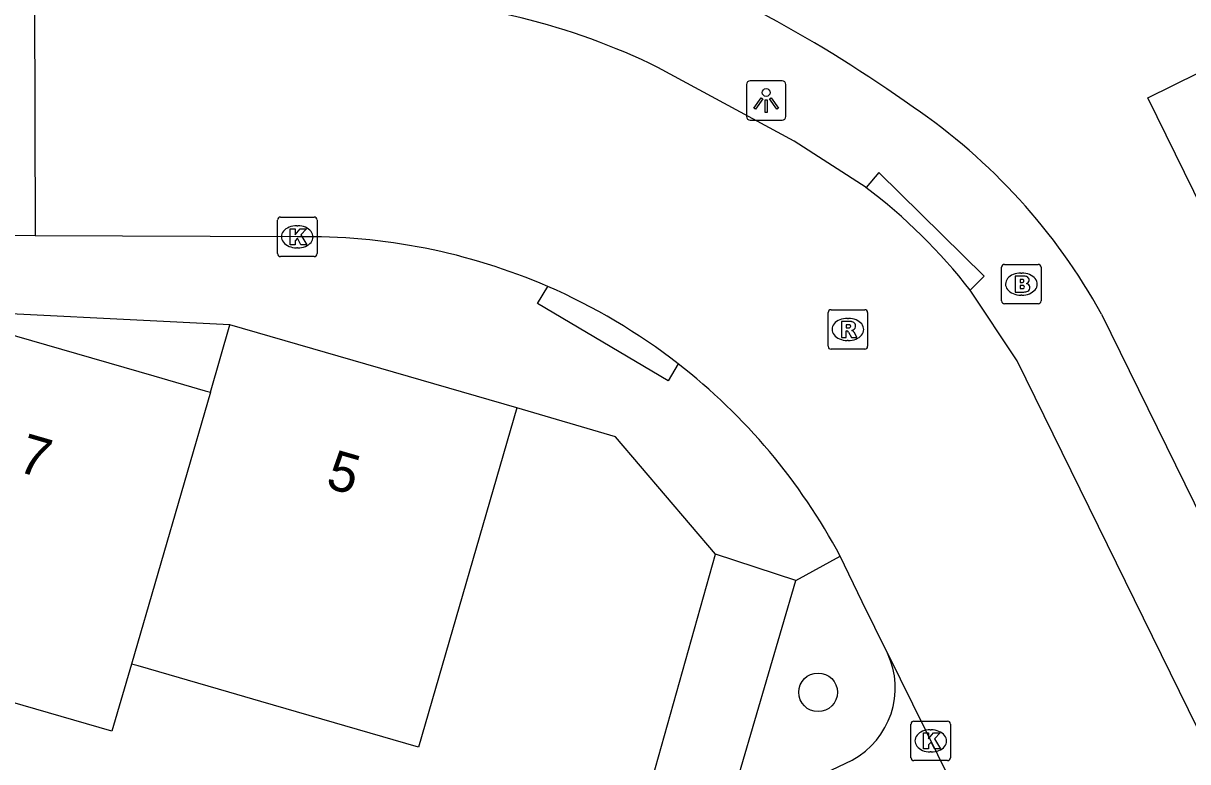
# Model space of a CAD drawing. Extents: x 159718 to 160783, y 383290 to 384030.
# Drawn here: x 160053.1 to 160082.59, y 383412.13 to 383430.82 of the extents above; entities that cross this region are included whole.
import ezdxf

# ---------------------------------------------------------------- set-up
doc = ezdxf.new("R2010")
doc.units = 0
for name, color, linetype in [('IMGEO_Boom', 7, 'Continuous'), ('IMGEO_Brandkraan', 7, 'Continuous'), ('IMGEO_Kolk', 7, 'Continuous'), ('IMGEO_Lichtpunt', 7, 'Continuous'), ('IMGEO_Pand', 7, 'Continuous'), ('IMGEO_Pand_nummerreeks', 7, 'Continuous'), ('IMGEO_Parkeervlak_open', 7, 'Continuous'), ('IMGEO_Rijbaan_lokaal_open', 7, 'Continuous'), ('IMGEO_Rioolput', 7, 'Continuous'), ('IMGEO_Voetpad_open', 7, 'Continuous')]:
    doc.layers.add(name, color=color, linetype=linetype)

msp = doc.modelspace()

# ---------------------------------------------------------------- linework, layer by layer
at = {"layer": 'IMGEO_Boom'}
msp.add_circle((160073.229, 383413.882), 0.489, dxfattribs=at)
at = {"layer": 'IMGEO_Brandkraan'}
for p, q in [((160077.875, 383423.791), (160077.875, 383424.643)), ((160077.95, 383424.717), (160078.802, 383424.717)), ((160078.876, 383424.643), (160078.876, 383423.791)), ((160078.363, 383424.497), (160078.388, 383424.497)), ((160078.802, 383423.717), (160077.95, 383423.717)), ((160078.386, 383423.937), (160078.361, 383423.937))]:
    msp.add_line(p, q, dxfattribs=at)
for points in [[(160077.875, 383423.791), (160077.875, 383424.643)], [(160077.95, 383424.717), (160078.802, 383424.717)], [(160078.876, 383424.643), (160078.876, 383423.791)], [(160078.223, 383424.417), (160078.223, 383424.017), (160078.436, 383424.017)], [(160078.454, 383424.417), (160078.223, 383424.417)], [(160078.402, 383424.336), (160078.348, 383424.336), (160078.348, 383424.26)], [(160078.348, 383424.26), (160078.401, 383424.26)], [(160078.41, 383424.184), (160078.348, 383424.184), (160078.348, 383424.103)], [(160078.348, 383424.103), (160078.41, 383424.103)], [(160078.802, 383423.717), (160077.95, 383423.717)]]:
    msp.add_lwpolyline(points, dxfattribs=at)
for centre, radius, start, end in [((160077.952, 383424.641), 0.0765, 91.552, 178.448), ((160077.952, 383424.641), 0.0765, 91.552, 178.448), ((160078.8, 383424.641), 0.0765, 1.552, 88.448), ((160078.8, 383424.641), 0.0765, 1.552, 88.448), ((160078.403, 383424.298), 0.0379, 267.8285, 90.9355), ((160078.458, 383424.272), 0.145, 59.4692, 91.5367), ((160078.483, 383424.319), 0.0922, 285.5137, 58.1501), ((160078.411, 383424.143), 0.0404, 269.8759, 90.5077), ((160078.442, 383424.268), 0.251, 268.6676, 293.5347), ((160078.488, 383424.127), 0.105, 301.3115, 78.989), ((160077.952, 383423.793), 0.0765, 181.552, 268.448), ((160077.952, 383423.793), 0.0765, 181.552, 268.448), ((160078.8, 383423.793), 0.0765, 271.552, 358.448), ((160078.8, 383423.793), 0.0765, 271.552, 358.448)]:
    msp.add_arc(centre, radius, start, end, dxfattribs=at)
for centre, major_axis, ratio, start_param, end_param in [((160078.362, 383424.217), (-0.387, 0.002), 0.722429, 4.712389, 7.853982), ((160078.387, 383424.217), (-0.39, 0.002), 0.717154, 1.570796, 4.712389)]:
    msp.add_ellipse(centre, major_axis=major_axis, ratio=ratio, start_param=start_param, end_param=end_param, dxfattribs=at)
at = {"layer": 'IMGEO_Kolk'}
for p, q in [((160059.54, 383424.988), (160059.54, 383425.84)), ((160059.615, 383425.914), (160060.467, 383425.914)), ((160060.541, 383425.84), (160060.541, 383424.988)), ((160060.028, 383425.694), (160060.053, 383425.694)), ((160060.051, 383425.134), (160060.026, 383425.134)), ((160060.467, 383424.914), (160059.615, 383424.914)), ((160075.581, 383412.227), (160075.581, 383413.079)), ((160075.656, 383413.153), (160076.508, 383413.153)), ((160076.582, 383413.079), (160076.582, 383412.227)), ((160076.069, 383412.933), (160076.094, 383412.933)), ((160076.092, 383412.373), (160076.067, 383412.373)), ((160076.508, 383412.153), (160075.656, 383412.153))]:
    msp.add_line(p, q, dxfattribs=at)
for points in [[(160059.54, 383424.988), (160059.54, 383425.84)], [(160059.615, 383425.914), (160060.467, 383425.914)], [(160060.541, 383425.84), (160060.541, 383424.988)], [(160059.861, 383425.614), (160059.984, 383425.614), (160059.984, 383425.463), (160060.114, 383425.614), (160060.278, 383425.614), (160060.132, 383425.463), (160060.285, 383425.214), (160060.133, 383425.214), (160060.048, 383425.378), (160059.984, 383425.311), (160059.984, 383425.214), (160059.861, 383425.214), (160059.861, 383425.614)], [(160060.467, 383424.914), (160059.615, 383424.914)], [(160075.581, 383412.227), (160075.581, 383413.079)], [(160075.656, 383413.153), (160076.508, 383413.153)], [(160076.582, 383413.079), (160076.582, 383412.227)], [(160075.902, 383412.853), (160076.025, 383412.853), (160076.025, 383412.702), (160076.155, 383412.853), (160076.319, 383412.853), (160076.173, 383412.702), (160076.326, 383412.453), (160076.174, 383412.453), (160076.089, 383412.617), (160076.025, 383412.55), (160076.025, 383412.453), (160075.902, 383412.453), (160075.902, 383412.853)], [(160076.508, 383412.153), (160075.656, 383412.153)]]:
    msp.add_lwpolyline(points, dxfattribs=at)
for centre, start, end in [((160059.617, 383425.838), 91.552, 178.448), ((160059.617, 383425.838), 91.552, 178.448), ((160060.465, 383425.838), 1.552, 88.448), ((160060.465, 383425.838), 1.552, 88.448), ((160059.617, 383424.99), 181.552, 268.448), ((160059.617, 383424.99), 181.552, 268.448), ((160060.465, 383424.99), 271.552, 358.448), ((160060.465, 383424.99), 271.552, 358.448), ((160075.658, 383413.077), 91.552, 178.448), ((160075.658, 383413.077), 91.552, 178.448), ((160076.506, 383413.077), 1.552, 88.448), ((160076.506, 383413.077), 1.552, 88.448), ((160075.658, 383412.229), 181.552, 268.448), ((160075.658, 383412.229), 181.552, 268.448), ((160076.506, 383412.229), 271.552, 358.448), ((160076.506, 383412.229), 271.552, 358.448)]:
    msp.add_arc(centre, 0.0765, start, end, dxfattribs=at)
for centre, major_axis, ratio, start_param, end_param in [((160060.027, 383425.414), (-0.387, 0.002), 0.722429, 4.712389, 7.853982), ((160060.052, 383425.414), (-0.39, 0.002), 0.717154, 1.570796, 4.712389), ((160076.068, 383412.653), (-0.387, 0.002), 0.722429, 4.712389, 7.853982), ((160076.093, 383412.653), (-0.39, 0.002), 0.717154, 1.570796, 4.712389)]:
    msp.add_ellipse(centre, major_axis=major_axis, ratio=ratio, start_param=start_param, end_param=end_param, dxfattribs=at)
at = {"layer": 'IMGEO_Lichtpunt'}
for p, q in [((160071.415, 383429.269), (160071.415, 383428.462)), ((160071.415, 383429.269), (160071.415, 383428.462)), ((160072.317, 383429.364), (160071.509, 383429.364)), ((160072.317, 383429.364), (160071.509, 383429.364)), ((160072.411, 383428.462), (160072.411, 383429.269)), ((160072.411, 383428.462), (160072.411, 383429.269)), ((160071.509, 383428.368), (160072.317, 383428.368)), ((160071.509, 383428.368), (160072.317, 383428.368))]:
    msp.add_line(p, q, dxfattribs=at)
for points in [[(160071.789, 383428.933), (160071.828, 383428.905), (160071.64, 383428.643), (160071.602, 383428.67), (160071.789, 383428.933)], [(160071.891, 383428.885), (160071.938, 383428.885), (160071.938, 383428.563), (160071.891, 383428.563), (160071.891, 383428.885)], [(160072.001, 383428.905), (160072.039, 383428.932), (160072.226, 383428.67), (160072.187, 383428.642), (160072.001, 383428.905)]]:
    msp.add_lwpolyline(points, dxfattribs=at)
msp.add_circle((160071.914, 383429.067), 0.0994, dxfattribs=at)
for centre, start, end in [((160071.509, 383429.269), 90, 180), ((160071.509, 383429.269), 90, 180), ((160072.317, 383429.269), 0, 90), ((160072.317, 383429.269), 0, 90), ((160071.509, 383428.462), 180, 270), ((160071.509, 383428.462), 180, 270), ((160072.317, 383428.462), 270, 0), ((160072.317, 383428.462), 270, 360)]:
    msp.add_arc(centre, 0.0946, start, end, dxfattribs=at)
at = {"layer": 'IMGEO_Pand'}
for points in [[(160084.135, 383423.723), (160081.575, 383428.935), (160086.063, 383431.14), (160088.858, 383432.513), (160091.41, 383427.319)], [(160050.589, 383423.578), (160056.413, 383421.892), (160057.713, 383421.516), (160057.84, 383421.479)], [(160057.84, 383421.479), (160058.335, 383423.186)], [(160065.601, 383421.083), (160058.335, 383423.186)], [(160057.84, 383421.479), (160055.843, 383414.597)], [(160065.601, 383421.083), (160063.114, 383412.492), (160059.121, 383413.649), (160058.312, 383413.883), (160056.011, 383414.549), (160055.843, 383414.597)], [(160055.843, 383414.597), (160055.35, 383412.897), (160053.1, 383413.548), (160048.31, 383414.935), (160048.2, 383414.967)]]:
    msp.add_lwpolyline(points, dxfattribs=at)
at = {"layer": 'IMGEO_Parkeervlak_open'}
msp.add_lwpolyline([(160082.854, 383393.924), (160080.28, 383392.663), (160071.343, 383410.855), (160074.095, 383412.165)], dxfattribs=at)
msp.add_arc((160073.094, 383413.996), 2.087, 298.6507, 24.7846, dxfattribs=at)
at = {"layer": 'IMGEO_Rijbaan_lokaal_open'}
for points in [[(160053.387, 383431.409), (160053.402, 383425.442)], [(160074.442, 383426.665), (160072.625, 383427.835), (160069.173, 383429.702)], [(160053.402, 383425.442), (160050.642, 383425.453)], [(160060.045, 383425.415), (160053.402, 383425.442)], [(160089.692, 383399.019), (160078.272, 383422.273), (160077.081, 383424.063)], [(160074.989, 383414.871), (160074.348, 383416.169), (160073.789, 383417.331)], [(160074.989, 383414.871), (160080.692, 383403.311), (160085.552, 383393.382)]]:
    msp.add_lwpolyline(points, dxfattribs=at)
for centre, radius, start, end in [((160061.713, 383414.51), 16.925, 63.848, 88.809), ((160065.687, 383415.146), 14.468, 38.0462, 52.7628), ((160060.308, 383410.15), 15.267, 66.5567, 90.987), ((160060.286, 383410.098), 15.324, 52.1458, 66.5604), ((160060.278, 383410.109), 15.32, 28.1254, 52.0946)]:
    msp.add_arc(centre, radius, start, end, dxfattribs=at)
at = {"layer": 'IMGEO_Rioolput'}
for p, q in [((160073.482, 383422.643), (160073.482, 383423.495)), ((160073.557, 383423.569), (160074.409, 383423.569)), ((160074.483, 383423.495), (160074.483, 383422.643)), ((160073.97, 383423.349), (160073.995, 383423.349)), ((160073.993, 383422.789), (160073.968, 383422.789)), ((160074.409, 383422.569), (160073.557, 383422.569))]:
    msp.add_line(p, q, dxfattribs=at)
for points in [[(160073.482, 383422.643), (160073.482, 383423.495)], [(160073.557, 383423.569), (160074.409, 383423.569)], [(160074.483, 383423.495), (160074.483, 383422.643)], [(160074.071, 383423.267), (160073.819, 383423.269), (160073.819, 383422.869)], [(160073.997, 383423.188), (160073.943, 383423.188), (160073.943, 383423.107)], [(160073.943, 383423.107), (160073.995, 383423.107)], [(160073.819, 383422.869), (160073.943, 383422.869), (160073.943, 383423.031), (160073.954, 383423.031)], [(160074.001, 383423.002), (160074.072, 383422.869), (160074.212, 383422.869), (160074.147, 383422.995)], [(160074.409, 383422.569), (160073.557, 383422.569)]]:
    msp.add_lwpolyline(points, dxfattribs=at)
for centre, radius, start, end in [((160073.559, 383423.493), 0.0765, 91.552, 178.448), ((160073.559, 383423.493), 0.0765, 91.552, 178.448), ((160074.407, 383423.493), 0.0765, 1.552, 88.448), ((160074.407, 383423.493), 0.0765, 1.552, 88.448), ((160073.979, 383423.296), 0.19, 274.7715, 282.9687), ((160074.003, 383423.092), 0.0964, 77.0061, 93.1865), ((160074.017, 383423.149), 0.0378, 276.6634, 79.6772), ((160074.07, 383423.157), 0.109, 350.3612, 89.416), ((160074.068, 383423.157), 0.112, 277.5842, 350.9817), ((160073.953, 383422.978), 0.0533, 26.0293, 88.6989), ((160074.052, 383422.942), 0.108, 29.5134, 73.7905), ((160073.559, 383422.645), 0.0765, 181.552, 268.448), ((160073.559, 383422.645), 0.0765, 181.552, 268.448), ((160074.407, 383422.645), 0.0765, 271.552, 358.448), ((160074.407, 383422.645), 0.0765, 271.552, 358.448)]:
    msp.add_arc(centre, radius, start, end, dxfattribs=at)
for centre, major_axis, ratio, start_param, end_param in [((160073.969, 383423.069), (-0.387, 0.002), 0.722429, 4.712389, 7.853982), ((160073.994, 383423.069), (-0.39, 0.002), 0.717154, 1.570796, 4.712389)]:
    msp.add_ellipse(centre, major_axis=major_axis, ratio=ratio, start_param=start_param, end_param=end_param, dxfattribs=at)
at = {"layer": 'IMGEO_Voetpad_open'}
for points in [[(160077.081, 383424.063), (160077.431, 383424.419), (160074.767, 383427.04), (160074.442, 383426.665)], [(160069.69, 383422.197), (160069.436, 383421.767), (160066.128, 383423.727), (160066.382, 383424.157)], [(160058.335, 383423.186), (160050.589, 383423.578)], [(160080.405, 383423.453), (160097.768, 383388.109)], [(160070.627, 383417.38), (160068.099, 383420.349), (160065.601, 383421.083)], [(160068.88, 383411.166), (160070.627, 383417.38)], [(160072.664, 383416.709), (160070.627, 383417.38)], [(160072.664, 383416.709), (160073.789, 383417.331)], [(160074.573, 383387.094), (160074.813, 383389.05), (160078.317, 383388.621), (160079.102, 383390.437), (160070.246, 383408.439), (160072.664, 383416.709)]]:
    msp.add_lwpolyline(points, dxfattribs=at)
for centre, radius, start, end in [((160054.691, 383399.299), 36.095, 54.5346, 68.3089), ((160067.075, 383416.118), 15.215, 28.823, 55.769)]:
    msp.add_arc(centre, radius, start, end, dxfattribs=at)

# ---------------------------------------------------------------- texts
at = {"layer": 'IMGEO_Pand_nummerreeks'}
for s, p in [('7', (160052.917, 383419.489)), ('5', (160060.728, 383419.078))]:
    msp.add_text(s, height=1, rotation=343.854, dxfattribs=at).set_placement(p)

doc.saveas('drawing.dxf')
